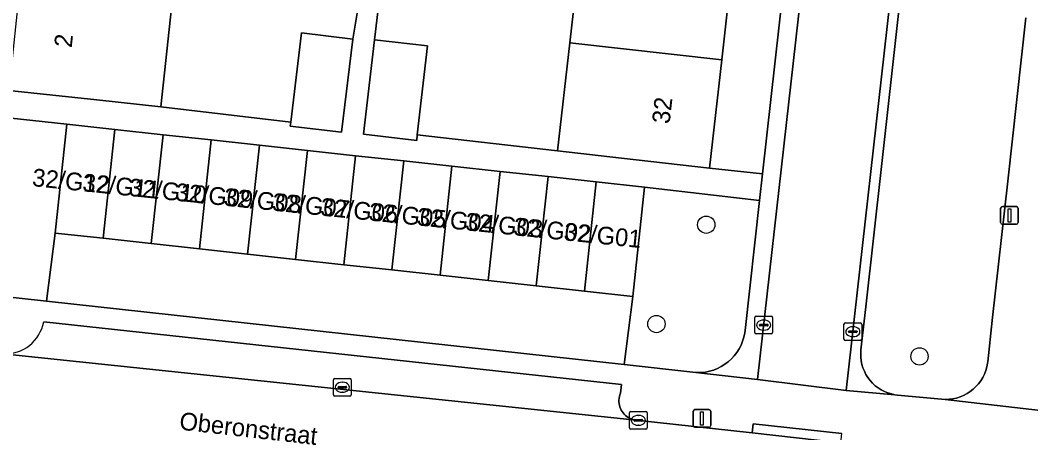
# Model space of a CAD drawing. Extents: x 161928 to 163071, y 386474 to 387428.
# Drawn here: x 162177.9 to 162235, y 386936.8 to 386960 of the extents above; entities that cross this region are included whole.
import ezdxf

# ---------------------------------------------------------------- set-up
doc = ezdxf.new("R2010")
doc.units = 0
for name, color, linetype in [('IMGEO_Boom', 7, 'Continuous'), ('IMGEO_Erf', 7, 'Continuous'), ('IMGEO_Groenvoorziening', 7, 'Continuous'), ('IMGEO_Kolk', 7, 'Continuous'), ('IMGEO_Lichtmast', 7, 'Continuous'), ('IMGEO_Openbare_ruimte_label', 7, 'Continuous'), ('IMGEO_Pand', 7, 'Continuous'), ('IMGEO_Pand_nummerreeks', 7, 'Continuous'), ('IMGEO_Parkeervlak_open', 7, 'Continuous'), ('IMGEO_Rijbaan_lokaal_open', 7, 'Continuous'), ('IMGEO_Voetpad_open', 7, 'Continuous')]:
    doc.layers.add(name, color=color, linetype=linetype)

msp = doc.modelspace()

# ---------------------------------------------------------------- linework, layer by layer
at = {"layer": 'IMGEO_Boom'}
for centre in [(162216.66, 386948.496), (162213.853, 386942.891), (162228.699, 386941.06)]:
    msp.add_circle(centre, 0.489, dxfattribs=at)
at = {"layer": 'IMGEO_Erf'}
msp.add_lwpolyline([(162225.21, 386999.368), (162222.252, 386999.728), (162221.546, 386993.453), (162220.911, 386987.808), (162220.236, 386981.808), (162219.564, 386975.832), (162218.89, 386969.847), (162218.206, 386963.768), (162217.534, 386957.795), (162216.848, 386951.694), (162219.842, 386951.359)], close=True, dxfattribs=at)
for points in [[(162198.179, 386960.973), (162197.93, 386958.933), (162200.926, 386958.591), (162200.352, 386953.563), (162208.273, 386952.659), (162208.959, 386958.76), (162209.631, 386964.732)], [(162186.546, 386961.449), (162185.872, 386955.155), (162193.205, 386954.273), (162193.812, 386959.322), (162196.716, 386958.973), (162197.073, 386961.107)]]:
    msp.add_lwpolyline(points, dxfattribs=at)
at = {"layer": 'IMGEO_Groenvoorziening'}
msp.add_lwpolyline([(162227.703, 386962.131), (162226.557, 386951.779), (162225.666, 386943.867), (162225.394, 386941.43), (162225.38, 386941.224), (162225.385, 386941.019), (162225.408, 386940.814), (162225.45, 386940.612), (162225.509, 386940.415), (162225.585, 386940.224), (162225.679, 386940.04), (162225.788, 386939.865), (162225.913, 386939.701), (162226.052, 386939.549), (162226.203, 386939.41), (162226.367, 386939.285), (162226.541, 386939.175), (162226.724, 386939.081), (162226.915, 386939.003), (162227.112, 386938.943), (162227.314, 386938.901), (162227.462, 386938.882), (162229.941, 386938.644), (162230.155, 386938.633), (162230.368, 386938.641), (162230.58, 386938.668), (162230.789, 386938.714), (162230.993, 386938.779), (162231.19, 386938.861), (162231.38, 386938.961), (162231.559, 386939.077), (162231.728, 386939.209), (162231.883, 386939.355), (162232.026, 386939.515), (162232.153, 386939.687), (162232.265, 386939.869), (162232.36, 386940.061), (162232.437, 386940.26), (162232.496, 386940.466), (162232.537, 386940.676), (162232.547, 386940.754), (162232.808, 386943.098), (162233.677, 386950.949), (162234.709, 386960.178)], dxfattribs=at)
for points in [[(162179.916, 386948.023), (162180.57, 386954.161), (162172.17, 386955.064), (162171.276, 386946.716), (162171.267, 386946.57), (162171.272, 386946.424), (162171.289, 386946.279), (162171.32, 386946.136), (162171.363, 386945.996), (162171.418, 386945.861), (162171.485, 386945.731), (162171.564, 386945.608), (162171.653, 386945.492), (162171.752, 386945.385), (162171.86, 386945.286), (162171.977, 386945.198), (162172.101, 386945.121), (162172.232, 386945.055), (162172.368, 386945.002), (162172.508, 386944.96), (162172.651, 386944.931), (162172.719, 386944.922), (162179.416, 386944.176)], [(162218.855, 386942.525), (162219.674, 386949.852), (162213.172, 386950.618), (162212.516, 386944.448), (162212.035, 386940.602), (162215.899, 386940.164), (162216.137, 386940.148), (162216.376, 386940.153), (162216.613, 386940.179), (162216.848, 386940.227), (162217.076, 386940.295), (162217.298, 386940.383), (162217.511, 386940.491), (162217.714, 386940.618), (162217.905, 386940.762), (162218.082, 386940.922), (162218.243, 386941.098), (162218.389, 386941.287), (162218.517, 386941.489), (162218.626, 386941.701), (162218.716, 386941.922), (162218.786, 386942.151), (162218.836, 386942.384)]]:
    msp.add_lwpolyline(points, close=True, dxfattribs=at)
at = {"layer": 'IMGEO_Kolk'}
for p, q in [((162219.405, 386942.404), (162219.405, 386943.256)), ((162219.48, 386943.33), (162220.332, 386943.33)), ((162219.664, 386942.824), (162219.664, 386942.836)), ((162219.707, 386942.873), (162220.105, 386942.873)), ((162219.893, 386943.11), (162219.918, 386943.11)), ((162220.148, 386942.836), (162220.148, 386942.824)), ((162220.406, 386943.256), (162220.406, 386942.404)), ((162224.436, 386942.03), (162224.436, 386942.882)), ((162224.511, 386942.956), (162225.363, 386942.956)), ((162225.437, 386942.882), (162225.437, 386942.03)), ((162220.332, 386942.33), (162219.48, 386942.33)), ((162220.102, 386942.787), (162219.704, 386942.787)), ((162219.916, 386942.55), (162219.891, 386942.55)), ((162224.695, 386942.45), (162224.695, 386942.462)), ((162225.133, 386942.413), (162224.735, 386942.413)), ((162224.738, 386942.499), (162225.136, 386942.499)), ((162224.924, 386942.736), (162224.949, 386942.736)), ((162225.179, 386942.462), (162225.179, 386942.45)), ((162225.363, 386941.956), (162224.511, 386941.956)), ((162224.947, 386942.176), (162224.922, 386942.176)), ((162195.62, 386938.895), (162195.62, 386939.747)), ((162195.695, 386939.821), (162196.547, 386939.821)), ((162196.108, 386939.601), (162196.133, 386939.601)), ((162196.621, 386939.747), (162196.621, 386938.895)), ((162195.879, 386939.315), (162195.879, 386939.327)), ((162196.317, 386939.278), (162195.919, 386939.278)), ((162195.922, 386939.364), (162196.32, 386939.364)), ((162196.131, 386939.041), (162196.106, 386939.041)), ((162196.363, 386939.327), (162196.363, 386939.315)), ((162196.547, 386938.821), (162195.695, 386938.821)), ((162212.33, 386937.03), (162212.33, 386937.882)), ((162212.405, 386937.956), (162213.257, 386937.956)), ((162212.818, 386937.736), (162212.843, 386937.736)), ((162213.331, 386937.882), (162213.331, 386937.03)), ((162212.589, 386937.45), (162212.589, 386937.462)), ((162213.027, 386937.413), (162212.629, 386937.413)), ((162212.632, 386937.499), (162213.03, 386937.499)), ((162212.841, 386937.176), (162212.816, 386937.176)), ((162213.073, 386937.462), (162213.073, 386937.45)), ((162213.257, 386936.956), (162212.405, 386936.956))]:
    msp.add_line(p, q, dxfattribs=at)
for points in [[(162219.405, 386942.404), (162219.405, 386943.256)], [(162219.48, 386943.33), (162220.332, 386943.33)], [(162220.406, 386943.256), (162220.406, 386942.404)], [(162224.436, 386942.03), (162224.436, 386942.882)], [(162224.511, 386942.956), (162225.363, 386942.956)], [(162225.437, 386942.882), (162225.437, 386942.03)], [(162220.332, 386942.33), (162219.48, 386942.33)], [(162225.363, 386941.956), (162224.511, 386941.956)], [(162195.62, 386938.895), (162195.62, 386939.747)], [(162195.695, 386939.821), (162196.547, 386939.821)], [(162196.621, 386939.747), (162196.621, 386938.895)], [(162196.547, 386938.821), (162195.695, 386938.821)], [(162212.33, 386937.03), (162212.33, 386937.882)], [(162212.405, 386937.956), (162213.257, 386937.956)], [(162213.331, 386937.882), (162213.331, 386937.03)], [(162213.257, 386936.956), (162212.405, 386936.956)]]:
    msp.add_lwpolyline(points, dxfattribs=at)
for centre, radius, start, end in [((162219.482, 386943.254), 0.0765, 91.552, 178.448), ((162219.482, 386943.254), 0.0765, 91.552, 178.448), ((162219.704, 386942.833), 0.0403, 85.8775, 175.7526), ((162220.109, 386942.835), 0.0386, 1.7309, 96.639), ((162220.33, 386943.254), 0.0765, 1.552, 88.448), ((162220.33, 386943.254), 0.0765, 1.552, 88.448), ((162224.513, 386942.88), 0.0765, 91.552, 178.448), ((162224.513, 386942.88), 0.0765, 91.552, 178.448), ((162225.361, 386942.88), 0.0765, 1.552, 88.448), ((162225.361, 386942.88), 0.0765, 1.552, 88.448), ((162219.482, 386942.406), 0.0765, 181.552, 268.448), ((162219.482, 386942.406), 0.0765, 181.552, 268.448), ((162219.701, 386942.823), 0.0366, 178.938, 274.7102), ((162220.105, 386942.83), 0.043, 264.8664, 352.4533), ((162220.33, 386942.406), 0.0765, 271.552, 358.448), ((162220.33, 386942.406), 0.0765, 271.552, 358.448), ((162224.735, 386942.459), 0.0403, 85.8775, 175.7526), ((162224.732, 386942.449), 0.0366, 178.938, 274.7102), ((162225.136, 386942.456), 0.043, 264.8664, 352.4533), ((162225.14, 386942.461), 0.0386, 1.7309, 96.639), ((162224.513, 386942.032), 0.0765, 181.552, 268.448), ((162224.513, 386942.032), 0.0765, 181.552, 268.448), ((162225.361, 386942.032), 0.0765, 271.552, 358.448), ((162225.361, 386942.032), 0.0765, 271.552, 358.448), ((162195.697, 386939.745), 0.0765, 91.552, 178.448), ((162195.697, 386939.745), 0.0765, 91.552, 178.448), ((162196.545, 386939.745), 0.0765, 1.552, 88.448), ((162196.545, 386939.745), 0.0765, 1.552, 88.448), ((162195.697, 386938.897), 0.0765, 181.552, 268.448), ((162195.697, 386938.897), 0.0765, 181.552, 268.448), ((162195.919, 386939.324), 0.0403, 85.8775, 175.7526), ((162195.916, 386939.314), 0.0366, 178.938, 274.7102), ((162196.32, 386939.321), 0.043, 264.8664, 352.4533), ((162196.324, 386939.326), 0.0386, 1.7309, 96.639), ((162196.545, 386938.897), 0.0765, 271.552, 358.448), ((162196.545, 386938.897), 0.0765, 271.552, 358.448), ((162212.407, 386937.88), 0.0765, 91.552, 178.448), ((162212.407, 386937.88), 0.0765, 91.552, 178.448), ((162213.255, 386937.88), 0.0765, 1.552, 88.448), ((162213.255, 386937.88), 0.0765, 1.552, 88.448), ((162212.629, 386937.459), 0.0403, 85.8775, 175.7526), ((162212.626, 386937.449), 0.0366, 178.938, 274.7102), ((162213.03, 386937.456), 0.043, 264.8664, 352.4533), ((162213.034, 386937.461), 0.0386, 1.7309, 96.639), ((162212.407, 386937.032), 0.0765, 181.552, 268.448), ((162212.407, 386937.032), 0.0765, 181.552, 268.448), ((162213.255, 386937.032), 0.0765, 271.552, 358.448), ((162213.255, 386937.032), 0.0765, 271.552, 358.448)]:
    msp.add_arc(centre, radius, start, end, dxfattribs=at)
for centre, major_axis, ratio, start_param, end_param in [((162219.892, 386942.83), (-0.387, 0.002), 0.722429, 4.712389, 7.853982), ((162219.917, 386942.83), (-0.39, 0.002), 0.717154, 1.570796, 4.712389), ((162224.923, 386942.456), (-0.387, 0.002), 0.722429, 4.712389, 7.853982), ((162224.948, 386942.456), (-0.39, 0.002), 0.717154, 1.570796, 4.712389), ((162196.107, 386939.321), (-0.387, 0.002), 0.722429, 4.712389, 7.853982), ((162196.132, 386939.321), (-0.39, 0.002), 0.717154, 1.570796, 4.712389), ((162212.817, 386937.456), (-0.387, 0.002), 0.722429, 4.712389, 7.853982), ((162212.842, 386937.456), (-0.39, 0.002), 0.717154, 1.570796, 4.712389)]:
    msp.add_ellipse(centre, major_axis=major_axis, ratio=ratio, start_param=start_param, end_param=end_param, dxfattribs=at)
at = {"layer": 'IMGEO_Lichtmast'}
for p, q in [((162233.275, 386948.621), (162233.275, 386949.421)), ((162233.275, 386949.421), (162233.275, 386948.621)), ((162233.375, 386949.521), (162234.165, 386949.521)), ((162234.165, 386949.521), (162233.375, 386949.521)), ((162234.265, 386949.421), (162234.265, 386948.621)), ((162234.265, 386948.621), (162234.265, 386949.421)), ((162234.165, 386948.521), (162233.375, 386948.521)), ((162233.375, 386948.521), (162234.165, 386948.521)), ((162215.925, 386937.163), (162215.925, 386937.963)), ((162215.925, 386937.963), (162215.925, 386937.163)), ((162216.025, 386938.063), (162216.815, 386938.063)), ((162216.815, 386938.063), (162216.025, 386938.063)), ((162216.915, 386937.963), (162216.915, 386937.163)), ((162216.915, 386937.163), (162216.915, 386937.963)), ((162216.815, 386937.063), (162216.025, 386937.063)), ((162216.025, 386937.063), (162216.815, 386937.063))]:
    msp.add_line(p, q, dxfattribs=at)
for points in [[(162233.695, 386949.396), (162233.845, 386949.396), (162233.845, 386948.646), (162233.695, 386948.646), (162233.695, 386949.396)], [(162216.345, 386937.938), (162216.495, 386937.938), (162216.495, 386937.188), (162216.345, 386937.188), (162216.345, 386937.938)]]:
    msp.add_lwpolyline(points, dxfattribs=at)
for centre, start, end in [((162233.375, 386949.421), 90, 180), ((162233.375, 386949.421), 90, 180), ((162234.165, 386949.421), 0, 90), ((162234.165, 386949.421), 360, 90), ((162233.375, 386948.621), 180, 270), ((162233.375, 386948.621), 180, 270), ((162234.165, 386948.621), 270, 0), ((162234.165, 386948.621), 270, 0), ((162216.025, 386937.963), 90, 180), ((162216.025, 386937.963), 90, 180), ((162216.815, 386937.963), 0, 90), ((162216.815, 386937.963), 360, 90), ((162216.025, 386937.163), 180, 270), ((162216.025, 386937.163), 180, 270), ((162216.815, 386937.163), 270, 0), ((162216.815, 386937.163), 270, 0)]:
    msp.add_arc(centre, 0.1, start, end, dxfattribs=at)
at = {"layer": 'IMGEO_Pand'}
for points in [[(162209.631, 386964.732), (162208.959, 386958.76), (162217.534, 386957.795), (162218.206, 386963.768)], [(162177.963, 386962.367), (162177.289, 386956.069), (162182.261, 386955.54), (162185.872, 386955.155), (162186.546, 386961.449)], [(162196.716, 386958.973), (162193.812, 386959.322), (162193.205, 386954.273), (162193.179, 386954.06), (162196.082, 386953.71)], [(162200.926, 386958.591), (162197.93, 386958.933), (162197.321, 386953.597), (162200.317, 386953.255), (162200.352, 386953.563)], [(162208.959, 386958.76), (162208.273, 386952.659), (162211.88, 386952.253), (162216.848, 386951.694), (162217.534, 386957.795)], [(162182.62, 386947.727), (162183.287, 386953.866), (162180.57, 386954.161), (162179.916, 386948.023)], [(162185.336, 386947.429), (162186.004, 386953.571), (162183.287, 386953.866), (162182.62, 386947.727)], [(162188.053, 386947.131), (162188.72, 386953.275), (162186.004, 386953.571), (162185.336, 386947.429)], [(162190.769, 386946.833), (162191.437, 386952.98), (162188.72, 386953.275), (162188.053, 386947.131)], [(162193.486, 386946.535), (162194.154, 386952.685), (162191.437, 386952.98), (162190.769, 386946.833)], [(162196.202, 386946.237), (162196.871, 386952.389), (162194.154, 386952.685), (162193.486, 386946.535)], [(162198.919, 386945.939), (162199.588, 386952.094), (162196.871, 386952.389), (162196.202, 386946.237)], [(162201.635, 386945.641), (162202.305, 386951.799), (162199.588, 386952.094), (162198.919, 386945.939)], [(162204.352, 386945.343), (162205.022, 386951.504), (162202.305, 386951.799), (162201.635, 386945.641)], [(162207.069, 386945.045), (162207.738, 386951.208), (162205.022, 386951.504), (162204.352, 386945.343)], [(162209.785, 386944.747), (162210.455, 386950.913), (162207.738, 386951.208), (162207.069, 386945.045)], [(162212.516, 386944.448), (162213.172, 386950.618), (162210.455, 386950.913), (162209.785, 386944.747)]]:
    msp.add_lwpolyline(points, close=True, dxfattribs=at)
at = {"layer": 'IMGEO_Parkeervlak_open'}
msp.add_lwpolyline([(162176.983, 386941.201), (162212.698, 386937.469), (162212.626, 386937.48), (162212.531, 386937.502), (162212.438, 386937.532), (162212.349, 386937.571), (162212.263, 386937.617), (162212.182, 386937.671), (162212.105, 386937.732), (162212.035, 386937.8), (162211.971, 386937.874), (162211.913, 386937.953), (162211.863, 386938.037), (162211.821, 386938.125), (162211.787, 386938.216), (162211.761, 386938.31), (162211.743, 386938.406), (162211.734, 386938.503), (162211.734, 386938.601), (162211.743, 386938.698), (162211.76, 386938.794), (162211.786, 386938.889), (162211.82, 386938.98), (162211.887, 386939.479), (162179.265, 386943.016)], dxfattribs=at)
msp.add_arc((162177.079, 386943.422), 2.223, 267.5156, 349.4787, dxfattribs=at)
at = {"layer": 'IMGEO_Rijbaan_lokaal_open'}
for points in [[(162226.169, 386998.452), (162219.56, 386939.75), (162224.563, 386939.135), (162227.167, 386962.37), (162230.152, 386989.011)], [(162281.687, 386929.52), (162276.59, 386930.123), (162250, 386933.34), (162241.491, 386934.282), (162224.263, 386936.189), (162219.254, 386936.743), (162212.698, 386937.469), (162176.983, 386941.201), (162175.3, 386941.368), (162174.718, 386936.398), (162175.881, 386936.251), (162250, 386928.164), (162274.027, 386925.3), (162282.029, 386924.397)]]:
    msp.add_lwpolyline(points, dxfattribs=at)
at = {"layer": 'IMGEO_Voetpad_open'}
for points in [[(162225.21, 386999.368), (162219.842, 386951.359), (162219.674, 386949.852), (162218.855, 386942.525), (162218.836, 386942.384), (162218.786, 386942.151), (162218.716, 386941.922), (162218.626, 386941.701), (162218.517, 386941.489), (162218.389, 386941.287), (162218.243, 386941.098), (162218.082, 386940.922), (162217.905, 386940.762), (162217.714, 386940.618), (162217.511, 386940.491), (162217.298, 386940.383), (162217.076, 386940.295), (162216.848, 386940.227), (162216.613, 386940.179), (162216.376, 386940.153), (162216.137, 386940.148), (162215.899, 386940.164), (162219.56, 386939.75), (162226.169, 386998.452)], [(162227.167, 386962.37), (162224.563, 386939.135), (162227.314, 386938.901), (162227.112, 386938.943), (162226.915, 386939.003), (162226.724, 386939.081), (162226.541, 386939.175), (162226.367, 386939.285), (162226.203, 386939.41), (162226.052, 386939.549), (162225.913, 386939.701), (162225.788, 386939.865), (162225.679, 386940.04), (162225.585, 386940.224), (162225.509, 386940.415), (162225.45, 386940.612), (162225.408, 386940.814), (162225.385, 386941.019), (162225.38, 386941.224), (162225.394, 386941.43), (162225.666, 386943.867), (162226.557, 386951.779), (162227.703, 386962.131)], [(162197.073, 386961.107), (162196.716, 386958.973), (162196.082, 386953.71), (162193.179, 386954.06), (162193.205, 386954.273), (162185.872, 386955.155), (162182.261, 386955.54), (162177.289, 386956.069)], [(162172.17, 386955.064), (162180.57, 386954.161), (162183.287, 386953.866), (162186.004, 386953.571), (162188.72, 386953.275), (162191.437, 386952.98), (162194.154, 386952.685), (162196.871, 386952.389), (162199.588, 386952.094), (162202.305, 386951.799), (162205.022, 386951.504), (162207.738, 386951.208), (162210.455, 386950.913), (162213.172, 386950.618), (162219.674, 386949.852), (162219.842, 386951.359), (162216.848, 386951.694), (162211.88, 386952.253), (162208.273, 386952.659), (162200.352, 386953.563), (162200.317, 386953.255), (162197.321, 386953.597), (162197.93, 386958.933), (162198.179, 386960.973)], [(162234.709, 386960.178), (162233.677, 386950.949), (162232.808, 386943.098), (162232.547, 386940.754), (162232.537, 386940.676), (162232.496, 386940.466), (162232.437, 386940.26), (162232.36, 386940.061), (162232.265, 386939.869), (162232.153, 386939.687), (162232.026, 386939.515), (162231.883, 386939.355), (162231.728, 386939.209), (162231.559, 386939.077), (162231.38, 386938.961), (162231.19, 386938.861), (162230.993, 386938.779), (162230.789, 386938.714), (162230.58, 386938.668), (162230.368, 386938.641), (162230.155, 386938.633), (162237.48, 386937.783)], [(162243.092, 386937.171), (162237.601, 386937.767), (162237.48, 386937.783), (162230.155, 386938.633), (162229.941, 386938.644), (162227.462, 386938.882), (162227.314, 386938.901), (162224.563, 386939.135), (162219.56, 386939.75), (162215.899, 386940.164), (162212.035, 386940.602), (162179.416, 386944.176), (162172.719, 386944.922), (162172.651, 386944.931), (162168.532, 386945.38)], [(162179.265, 386943.016), (162211.887, 386939.479), (162211.82, 386938.98), (162211.786, 386938.889), (162211.76, 386938.794), (162211.743, 386938.698), (162211.734, 386938.601), (162211.734, 386938.503), (162211.743, 386938.406), (162211.761, 386938.31), (162211.787, 386938.216), (162211.821, 386938.125), (162211.863, 386938.037), (162211.913, 386937.953), (162211.971, 386937.874), (162212.035, 386937.8), (162212.105, 386937.732), (162212.182, 386937.671), (162212.263, 386937.617), (162212.349, 386937.571), (162212.438, 386937.532), (162212.531, 386937.502), (162212.626, 386937.48), (162212.698, 386937.469), (162219.254, 386936.743), (162219.31, 386937.261), (162224.319, 386936.707)]]:
    msp.add_lwpolyline(points, dxfattribs=at)
for points in [[(162207.069, 386945.045), (162204.352, 386945.343), (162201.635, 386945.641), (162198.919, 386945.939), (162196.202, 386946.237), (162193.486, 386946.535), (162190.769, 386946.833), (162188.053, 386947.131), (162185.336, 386947.429), (162182.62, 386947.727), (162179.916, 386948.023), (162179.416, 386944.176), (162212.035, 386940.602), (162212.516, 386944.448), (162209.785, 386944.747)], [(162224.263, 386936.189), (162224.319, 386936.707), (162219.31, 386937.261), (162219.254, 386936.743)]]:
    msp.add_lwpolyline(points, close=True, dxfattribs=at)
msp.add_arc((162177.079, 386943.422), 2.223, 267.5156, 349.4787, dxfattribs=at)

# ---------------------------------------------------------------- texts
at = {"layer": 'IMGEO_Openbare_ruimte_label'}
msp.add_text('Oberonstraat', height=1, rotation=353.5713, dxfattribs=at).set_placement((162186.888, 386936.936))
at = {"layer": 'IMGEO_Pand_nummerreeks'}
for s, rotation, p in [('2', 83.8874, (162180.843, 386958.457)), ('32', 83.581, (162214.589, 386954.154)), ('32/G12', 354.181, (162178.58, 386950.679)), ('32/G11', 354.181, (162181.422, 386950.39)), ('32/G10', 354.181, (162184.041, 386950.123)), ('32/G09', 354.181, (162186.67, 386949.855)), ('32/G08', 354.181, (162189.402, 386949.577)), ('32/G07', 354.181, (162192.124, 386949.299)), ('32/G06', 354.181, (162194.85, 386949.021)), ('32/G05', 354.181, (162197.575, 386948.744)), ('32/G04', 354.181, (162200.301, 386948.466)), ('32/G03', 354.181, (162203.027, 386948.188)), ('32/G02', 354.181, (162205.746, 386947.911)), ('32/G01', 354.181, (162208.588, 386947.621))]:
    msp.add_text(s, height=1, rotation=rotation, dxfattribs=at).set_placement(p)

doc.saveas('drawing.dxf')
